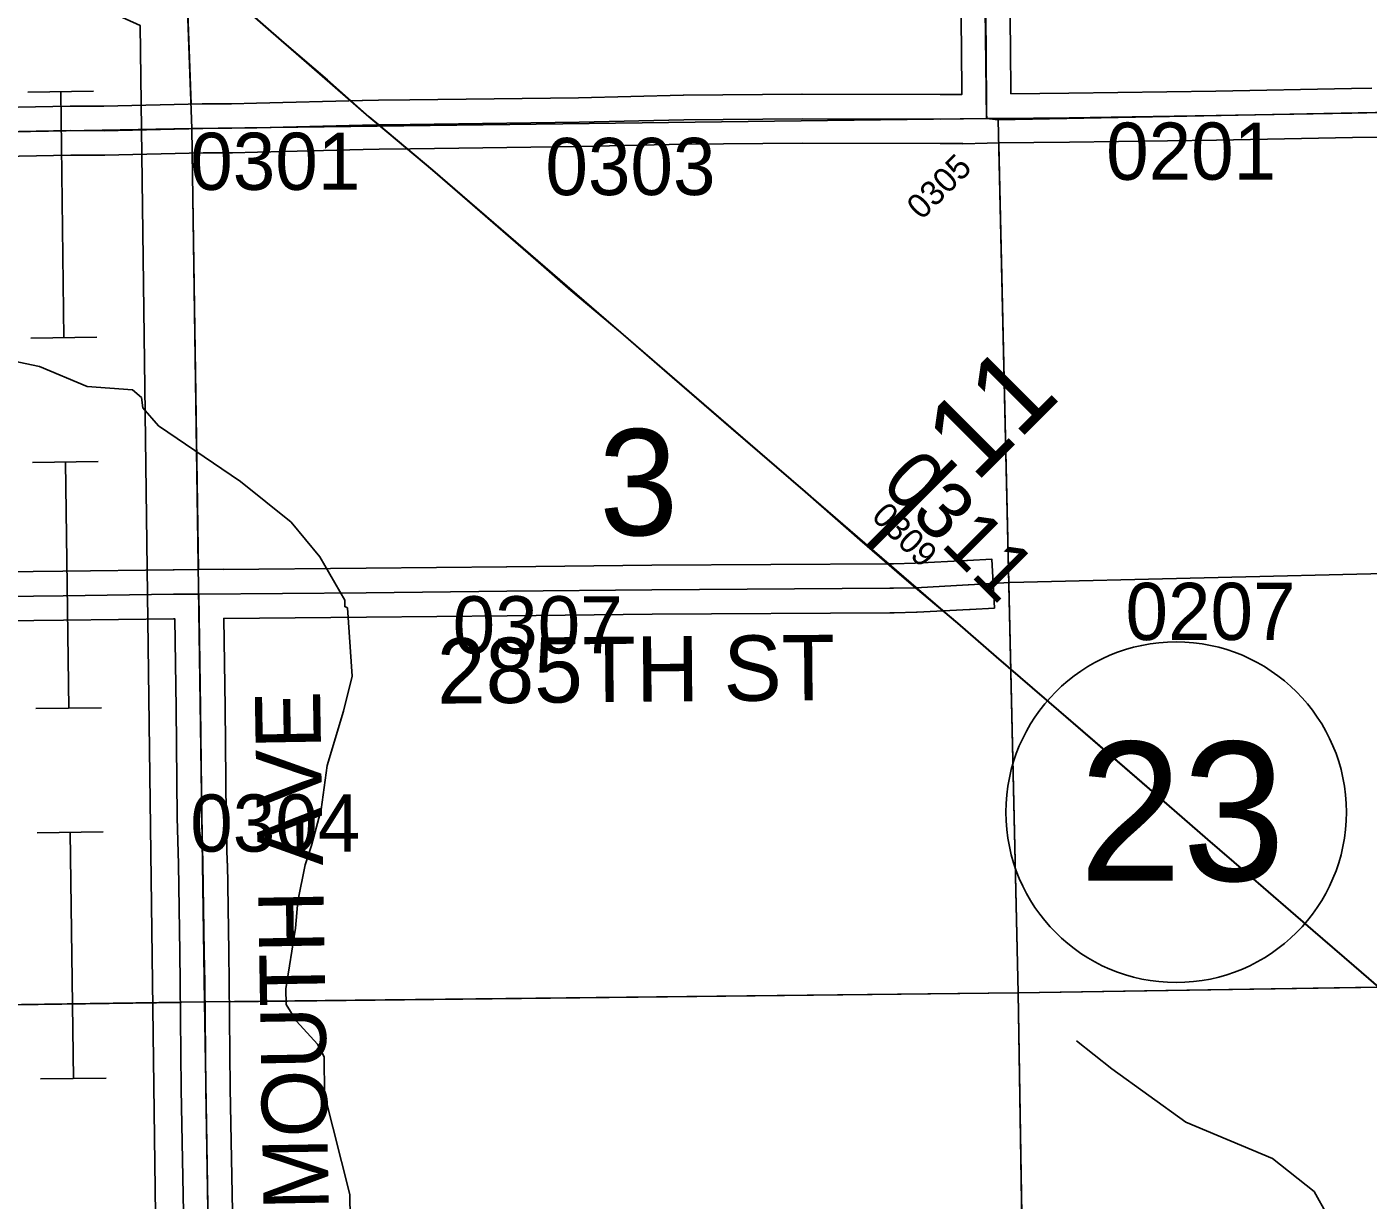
# Model space of a CAD drawing. Extents: x 23.6 to 68.7, y -63 to -29.
# Drawn here: x 47.529 to 49.171, y -52.848 to -51.412 of the extents above; entities that cross this region are included whole.
import ezdxf

# ---------------------------------------------------------------- set-up
doc = ezdxf.new("R2010")
doc.units = 0
for name, color, linetype in [('tdCoHydroRiver', 7, 'Continuous'), ('tdCoPipe', 7, 'Continuous'), ('tdCoPriCL', 7, 'Continuous'), ('tdCoPrimary', 7, 'Continuous'), ('tdCoPriNonDiv', 7, 'Continuous'), ('tdCoPriNonDivCL', 7, 'Continuous'), ('tdCoSecRdNmbr', 7, 'Continuous'), ('tdCoSecRdTxt', 7, 'Continuous'), ('tdCoSecRteBand', 7, 'Continuous'), ('tdCoSecRteCL', 7, 'Continuous'), ('tdCoSectLine', 7, 'Continuous'), ('tdCoSectLinePart', 7, 'Continuous'), ('tdCoSectNmbr', 7, 'Continuous'), ('tdCoShieldStRte', 7, 'Continuous'), ('tdCoSurfGravel', 7, 'Continuous'), ('tdCoSurfLNO', 7, 'Continuous'), ('tdCoTwpBndryShd', 7, 'Continuous'), ('tdStHwyPriRefPost1', 7, 'Continuous')]:
    doc.layers.add(name, color=color, linetype=linetype)

msp = doc.modelspace()

# ---------------------------------------------------------------- linework, layer by layer
at = {"layer": 'tdCoHydroRiver'}
for points in [[(47.9252, -52.8997), (47.9245, -52.8413), (47.8932, -52.7185), (47.8927, -52.6728), (47.8846, -52.6571), (47.8591, -52.6289), (47.8462, -52.6085), (47.846, -52.5896), (47.8578, -52.5153), (47.8606, -52.4821), (47.8696, -52.4378), (47.8772, -52.414), (47.8894, -52.3697), (47.8967, -52.316), (47.9165, -52.2494), (47.9271, -52.2067), (47.9214, -52.1231), (47.9182, -52.1215), (47.9181, -52.1137), (47.8876, -52.0603), (47.8524, -52.0181), (47.7903, -51.9682), (47.6901, -51.8999), (47.6709, -51.878), (47.6692, -51.8654), (47.658, -51.856), (47.6027, -51.8519), (47.5441, -51.8273), (47.4934, -51.8168)], [(49.1807, -52.9507), (49.1472, -52.9179), (49.136, -52.9038), (49.1359, -52.8975), (49.1295, -52.8913), (49.1214, -52.8661), (49.1053, -52.8378), (49.0543, -52.7974), (48.9481, -52.7527), (48.8574, -52.6874), (48.8144, -52.6532)]]:
    msp.add_lwpolyline(points, dxfattribs=at)
at = {"layer": 'tdCoPipe'}
for p, q in [((47.5299, -51.4914), (47.6104, -51.4904)), ((47.5338, -51.7928), (47.6145, -51.7917)), ((47.5358, -51.9449), (47.6163, -51.9439)), ((47.5396, -52.2462), (47.6203, -52.2452)), ((47.5416, -52.3984), (47.6221, -52.3974)), ((47.5455, -52.6997), (47.6261, -52.6987))]:
    msp.add_line(p, q, dxfattribs=at)
for points in [[(47.6047, -46.6586), (47.5572, -46.6597), (47.5935, -51.1509), (47.5318, -51.225), (47.5319, -51.3484), (47.5319, -51.3484), (47.6677, -51.41), (47.7455, -57.4574)], [(47.5702, -51.4909), (47.5741, -51.7922)], [(47.5761, -51.9444), (47.58, -52.2457)], [(47.5819, -52.3979), (47.5858, -52.6992)]]:
    msp.add_lwpolyline(points, dxfattribs=at)
at = {"layer": 'tdCoPriCL'}
msp.add_lwpolyline([(49.1885, -52.5912), (49.1541, -52.5615), (49.1038, -52.518), (49.0216, -52.4471), (48.9749, -52.4065), (48.9153, -52.3546), (48.8363, -52.2866), (48.7328, -52.1973), (48.716, -52.1828), (48.6684, -52.1416), (48.6172, -52.0984), (48.6033, -52.0866), (48.549, -52.0395), (48.4819, -51.9811), (48.3914, -51.9031), (48.3189, -51.8405), (48.2561, -51.786), (48.1949, -51.7345), (48.152, -51.697), (48.0684, -51.6242), (48.0257, -51.5872), (47.9593, -51.5315), (47.9476, -51.5216), (47.8965, -51.4765), (47.8437, -51.4311), (47.7922, -51.386)], dxfattribs=at)
at = {"layer": 'tdCoPrimary'}
msp.add_lwpolyline([(49.2383, -52.6339), (49.1545, -52.5615), (49.1042, -52.518), (49.022, -52.4471), (48.9753, -52.4065), (48.9157, -52.3546), (48.8367, -52.2866), (48.7164, -52.1828), (48.6688, -52.1416), (48.6176, -52.0984), (48.6037, -52.0866), (48.5494, -52.0395), (48.4823, -51.9811), (48.3918, -51.9031), (48.3193, -51.8405), (48.2564, -51.7858), (48.2564, -51.786), (48.1953, -51.7345), (48.1524, -51.697), (48.0688, -51.6242), (48.0261, -51.5872), (47.9597, -51.5315), (47.9479, -51.5216), (47.8969, -51.4765), (47.8441, -51.4311), (47.7926, -51.386)], dxfattribs=at)
msp.add_lwpolyline([(49.2383, -52.6339), (49.1545, -52.5615), (49.1042, -52.518), (49.022, -52.4471), (48.9753, -52.4065), (48.9157, -52.3546), (48.8367, -52.2866), (48.7164, -52.1828), (48.6688, -52.1416), (48.6176, -52.0984), (48.6037, -52.0866), (48.5494, -52.0395), (48.4823, -51.9811), (48.3918, -51.9031), (48.3193, -51.8405), (48.2564, -51.7858), (48.2564, -51.786), (48.1953, -51.7345), (48.1524, -51.697), (48.0688, -51.6242), (48.0261, -51.5872), (47.9597, -51.5315), (47.9479, -51.5216), (47.8969, -51.4765), (47.8441, -51.4311), (47.7926, -51.386)], dxfattribs=at)
msp.add_lwpolyline([(49.2383, -52.6339), (49.1545, -52.5615), (49.1042, -52.518), (49.022, -52.4471), (48.9753, -52.4065), (48.9157, -52.3546), (48.8367, -52.2866), (48.7164, -52.1828), (48.6688, -52.1416), (48.6176, -52.0984), (48.6037, -52.0866), (48.5494, -52.0395), (48.4823, -51.9811), (48.3918, -51.9031), (48.3193, -51.8405), (48.2564, -51.7858), (48.2564, -51.786), (48.1953, -51.7345), (48.1524, -51.697), (48.0688, -51.6242), (48.0261, -51.5872), (47.9597, -51.5315), (47.9479, -51.5216), (47.8969, -51.4765), (47.8441, -51.4311), (47.7926, -51.386)], dxfattribs=at)
at = {"layer": 'tdCoPriNonDiv'}
msp.add_lwpolyline([(49.8073, -53.1241), (49.1541, -52.5615), (48.6684, -52.1416), (48.2561, -51.786), (48.0258, -51.5872), (47.9476, -51.5216), (47.7922, -51.386), (47.4933, -51.1305), (47.2517, -50.9216), (47.0504, -50.75), (46.8721, -50.5978), (46.6907, -50.4385), (46.5932, -50.3553), (46.427, -50.2102), (46.3188, -50.1179), (46.2717, -50.0765), (46.1163, -49.9424), (45.9086, -49.7346)], dxfattribs=at)
at = {"layer": 'tdCoPriNonDivCL'}
msp.add_lwpolyline([(49.2379, -52.6339), (49.1541, -52.5615), (49.1038, -52.518), (49.0216, -52.4471), (48.9749, -52.4065), (48.9153, -52.3546), (48.8363, -52.2866), (48.716, -52.1828), (48.6684, -52.1416), (48.6172, -52.0984), (48.6033, -52.0866), (48.549, -52.0395), (48.4819, -51.9811), (48.3914, -51.9031), (48.3189, -51.8405), (48.2561, -51.7858), (48.2561, -51.786), (48.1949, -51.7345), (48.152, -51.697), (48.0684, -51.6242), (48.0257, -51.5872), (47.9593, -51.5315), (47.9476, -51.5216), (47.8965, -51.4765), (47.8437, -51.4311), (47.7922, -51.386)], dxfattribs=at)
msp.add_lwpolyline([(49.2379, -52.6339), (49.1541, -52.5615), (49.1038, -52.518), (49.0216, -52.4471), (48.9749, -52.4065), (48.9153, -52.3546), (48.8363, -52.2866), (48.716, -52.1828), (48.6684, -52.1416), (48.6172, -52.0984), (48.6033, -52.0866), (48.549, -52.0395), (48.4819, -51.9811), (48.3914, -51.9031), (48.3189, -51.8405), (48.2561, -51.7858), (48.2561, -51.786), (48.1949, -51.7345), (48.152, -51.697), (48.0684, -51.6242), (48.0257, -51.5872), (47.9593, -51.5315), (47.9476, -51.5216), (47.8965, -51.4765), (47.8437, -51.4311), (47.7922, -51.386)], dxfattribs=at)
at = {"layer": 'tdCoSecRteBand'}
for points in [[(47.4545, -51.5111), (47.5819, -51.5086), (47.5823, -51.5086), (47.5826, -51.5086), (47.6231, -51.5088), (47.7434, -51.5058), (47.7437, -51.5058), (47.744, -51.5058), (47.7796, -51.5056), (47.8099, -51.505), (47.9393, -51.5018), (47.9395, -51.5018), (47.9397, -51.5018), (47.9593, -51.5015), (47.9978, -51.501), (48.2044, -51.4983), (48.3327, -51.4953), (48.3329, -51.4953), (48.3331, -51.4953), (48.4781, -51.494), (48.4783, -51.494), (48.4784, -51.494), (48.6474, -51.4945), (48.6739, -51.4942), (48.6735, -51.4369), (48.6723, -51.3485)], [(48.7323, -51.3478), (48.7335, -51.4362), (48.7335, -51.4363), (48.7335, -51.4363), (48.7339, -51.4936)], [(48.7339, -51.4936), (48.734, -51.4936), (48.805, -51.4928), (48.9849, -51.4902), (49.151, -51.4872), (49.176, -51.4867)], [(49.1845, -51.5465), (49.1522, -51.5472), (49.1522, -51.5472), (49.1521, -51.5472), (48.9859, -51.5502), (48.9859, -51.5502), (48.9858, -51.5502), (48.8058, -51.5528), (48.8057, -51.5528), (48.8057, -51.5528), (48.7183, -51.5537), (48.7048, -51.5539), (48.675, -51.5546), (48.675, -51.5542), (48.6478, -51.5545), (48.6476, -51.5545), (48.6474, -51.5545), (48.4785, -51.554), (48.3338, -51.5553), (48.2056, -51.5582), (48.2055, -51.5582), (48.2054, -51.5582), (47.9986, -51.561), (47.9986, -51.561), (47.9986, -51.561), (47.9601, -51.5615), (47.9406, -51.5617), (47.8113, -51.5649), (47.8113, -51.5649), (47.8112, -51.5649), (47.7806, -51.5656), (47.7804, -51.5656), (47.7801, -51.5656), (47.7446, -51.5658), (47.6242, -51.5688), (47.6238, -51.5688), (47.6233, -51.5688), (47.5827, -51.5686), (47.4555, -51.5711)], [(47.3916, -52.0801), (47.573, -52.0781), (47.7078, -52.0764), (47.7079, -52.0764), (47.708, -52.0764), (47.7093, -52.0764), (47.7392, -52.0761), (47.7691, -52.0757), (47.7691, -52.0759), (47.7693, -52.0759), (47.9442, -52.0744), (48.1165, -52.0727), (48.1165, -52.0727), (48.1165, -52.0727), (48.294, -52.0709), (48.2941, -52.0709), (48.2941, -52.0709), (48.5855, -52.069), (48.5855, -52.069), (48.5856, -52.069), (48.59, -52.0689), (48.6165, -52.0684), (48.6801, -52.0649), (48.6806, -52.0649), (48.7105, -52.0633), (48.7138, -52.1232), (48.6839, -52.1248), (48.6834, -52.1249), (48.6193, -52.1284), (48.6187, -52.1284), (48.6182, -52.1284), (48.5909, -52.1289), (48.5907, -52.1289), (48.5904, -52.1289), (48.5858, -52.129), (48.2946, -52.1309), (48.1171, -52.1326), (47.9448, -52.1344), (47.9448, -52.1344), (47.9448, -52.1344), (47.7699, -52.1359), (47.7715, -52.2448), (47.7715, -52.2449), (47.7715, -52.2449), (47.773, -52.3783), (47.7743, -52.4355), (47.7743, -52.4356), (47.7744, -52.4357), (47.7761, -52.5443), (47.7761, -52.5444), (47.7761, -52.5445), (47.7766, -52.5814), (47.7766, -52.5814), (47.7766, -52.5815), (47.7779, -52.7113), (47.7809, -52.8839)], [(47.721, -52.8849), (47.7179, -52.7123), (47.7179, -52.7122), (47.7179, -52.7121), (47.7166, -52.5821), (47.7161, -52.5452), (47.7144, -52.4368), (47.713, -52.3795), (47.713, -52.3793), (47.713, -52.3791), (47.7115, -52.2457), (47.7099, -52.1364), (47.7085, -52.1364), (47.5737, -52.1381), (47.5737, -52.1381), (47.5737, -52.1381), (47.3922, -52.1401)]]:
    msp.add_lwpolyline(points, dxfattribs=at)
at = {"layer": 'tdCoSecRteCL'}
for points in [[(48.7043, -51.5239), (48.7041, -51.5171), (48.7035, -51.4366), (48.7023, -51.3481), (48.7015, -51.2538), (48.7003, -51.1515), (48.6994, -51.0484), (48.6977, -50.9522), (48.6959, -50.8442), (48.6954, -50.7492), (48.6939, -50.6326), (48.6926, -50.547), (48.6921, -50.5199)], [(48.7043, -51.5239), (48.718, -51.5237), (48.8054, -51.5228), (48.9854, -51.5202), (49.1516, -51.5172), (49.2065, -51.5161)], [(46.8485, -51.5519), (46.8522, -51.5518), (46.8896, -51.5524), (46.9323, -51.5514), (47.0134, -51.5508), (47.0885, -51.5493), (47.2004, -51.5463), (47.2721, -51.5449), (47.3844, -51.5417), (47.4549, -51.5411), (47.5825, -51.5386), (47.6235, -51.5388), (47.7441, -51.5358), (47.78, -51.5356), (47.8106, -51.535), (47.94, -51.5318), (47.9597, -51.5315), (47.9982, -51.531), (48.205, -51.5282), (48.3334, -51.5253), (48.4784, -51.524), (48.6475, -51.5245), (48.7043, -51.5239)], [(46.9835, -52.1126), (47.008, -52.1118), (47.1523, -52.1121), (47.2751, -52.1111), (47.3919, -52.1101), (47.5733, -52.1081), (47.7082, -52.1064), (47.7395, -52.1061)], [(47.7395, -52.1061), (47.9445, -52.1044), (48.1168, -52.1027), (48.2943, -52.1009), (48.5857, -52.099), (48.5903, -52.0989), (48.6176, -52.0984), (48.6818, -52.0949), (48.6822, -52.0949)], [(47.7542, -53.1048), (47.7538, -53.081), (47.7532, -53.0401), (47.751, -52.8844), (47.7479, -52.7118), (47.7466, -52.5818), (47.7461, -52.5448), (47.7444, -52.4362), (47.743, -52.3788), (47.7415, -52.2453), (47.7395, -52.1061)]]:
    msp.add_lwpolyline(points, dxfattribs=at)
at = {"layer": 'tdCoSectLine'}
for points in [[(48.6917, -50.5199), (48.704, -51.5239)], [(47.6946, -50.539), (47.7309, -51.5361)], [(48.7183, -51.5255), (49.7053, -51.5063)], [(47.7309, -51.5361), (48.704, -51.5239)], [(48.704, -51.5239), (48.7183, -51.5255)], [(48.7183, -51.5255), (48.743, -52.5943)], [(46.7201, -51.5546), (47.7309, -51.5361)], [(47.7309, -51.5361), (47.7464, -52.6056)], [(48.743, -52.5943), (49.7398, -52.579)], [(47.7464, -52.6056), (48.743, -52.5943)], [(48.743, -52.5943), (48.7589, -53.5904)], [(46.7374, -52.6201), (47.7464, -52.6056)], [(47.7464, -52.6056), (47.7625, -53.6025)]]:
    msp.add_lwpolyline(points, dxfattribs=at)
at = {"layer": 'tdCoSectLinePart'}
for points in [[(47.6956, -50.5685), (47.7299, -51.5064)], [(48.719, -51.5555), (48.743, -52.5943)], [(47.7314, -51.5664), (47.7388, -52.0765)], [(47.7765, -52.6053), (48.743, -52.5943)], [(48.743, -52.5943), (49.2076, -52.5872)], [(48.743, -52.5943), (48.7505, -53.0635)], [(47.0206, -52.6161), (47.7167, -52.6061)]]:
    msp.add_lwpolyline(points, dxfattribs=at)
at = {"layer": 'tdCoShieldStRte'}
msp.add_circle((48.9363, -52.3732), 0.2085, dxfattribs=at)
at = {"layer": 'tdCoSurfGravel'}
for points in [[(48.7043, -51.5239), (48.7041, -51.5171), (48.7035, -51.4366), (48.7023, -51.3481)], [(47.9597, -51.5315), (47.9982, -51.531), (48.205, -51.5282), (48.3334, -51.5253), (48.4784, -51.524), (48.6475, -51.5245), (48.7043, -51.5239), (48.718, -51.5237), (48.8054, -51.5228), (48.9854, -51.5202), (49.1516, -51.5172), (49.2065, -51.5161)], [(46.8333, -51.56), (46.8356, -51.5578), (46.8401, -51.5539), (46.8447, -51.5521), (46.8485, -51.5519), (46.8522, -51.5518), (46.8896, -51.5524), (46.9323, -51.5514), (47.0134, -51.5508), (47.0885, -51.5493), (47.2004, -51.5463), (47.2721, -51.5449), (47.3844, -51.5417), (47.4549, -51.5411), (47.5825, -51.5386), (47.6235, -51.5388), (47.7441, -51.5358), (47.78, -51.5356), (47.8106, -51.535), (47.94, -51.5318), (47.9597, -51.5315)], [(46.9835, -52.1126), (47.008, -52.1118), (47.1523, -52.1121), (47.2751, -52.1111), (47.3919, -52.1101), (47.5733, -52.1081), (47.7082, -52.1064), (47.7395, -52.1061)], [(47.7395, -52.1061), (47.9445, -52.1044), (48.1168, -52.1027), (48.2943, -52.1009), (48.5857, -52.099), (48.5903, -52.0989), (48.6176, -52.0984)], [(47.7572, -53.2872), (47.756, -53.2088), (47.7542, -53.1048), (47.7538, -53.081), (47.7532, -53.0401), (47.751, -52.8844), (47.7479, -52.7118), (47.7466, -52.5818), (47.7461, -52.5448), (47.7444, -52.4362), (47.743, -52.3788), (47.7415, -52.2453), (47.7395, -52.1061)], [(48.6176, -52.0984), (48.6818, -52.0949), (48.6822, -52.0949)]]:
    msp.add_lwpolyline(points, dxfattribs=at)
at = {"layer": 'tdCoSurfLNO'}
for p, q in [((48.7328, -52.0921), (49.2229, -52.0801)), ((48.6822, -52.0949), (48.7328, -52.0921))]:
    msp.add_line(p, q, dxfattribs=at)
at = {"layer": 'tdCoTwpBndryShd'}
msp.add_lwpolyline([(45.7019, -51.569), (46.6986, -51.5546), (46.7201, -51.5546), (47.7309, -51.5361), (48.704, -51.5239), (48.7183, -51.5255), (49.7053, -51.5063), (50.7061, -51.4863), (51.7147, -51.4711), (52.7049, -51.4551)], dxfattribs=at)

# ---------------------------------------------------------------- texts
at = {"layer": 'tdCoSecRdNmbr'}
for s, height, rotation, p in [('0201', 0.07, 0.038, (48.8506, -51.5988)), ('0301', 0.07, 0.0371, (47.7289, -51.6112)), ('0303', 0.07, 0.0375, (48.1639, -51.6176)), ('0305', 0.03, 45.037, (48.6247, -51.649)), ('0311', 0.07, 315.0371, (48.5727, -51.9729)), ('0309', 0.03, 315.0371, (48.5619, -52.0123)), ('0207', 0.07, 0.038, (48.8743, -52.1624)), ('0307', 0.07, 0.0374, (48.0503, -52.1788)), ('0304', 0.07, 0.0371, (47.7289, -52.4215))]:
    msp.add_text(s, height=height, rotation=rotation, dxfattribs=at).set_placement(p)
at = {"layer": 'tdCoSecRdTxt'}
for s, rotation, p in [('285TH ST', 0.5255, (48.0314, -52.2403)), ('PLYMOUTH AVE', 90.9661, (47.902, -53.0622))]:
    msp.add_text(s, height=0.08, rotation=rotation, dxfattribs=at).set_placement(p)
at = {"layer": 'tdCoSectNmbr'}
msp.add_text('3', height=0.13, rotation=1.0374, dxfattribs=at).set_placement((48.2304, -52.035))
at = {"layer": 'tdCoShieldStRte'}
msp.add_text('23', height=0.17, dxfattribs=at).set_placement((48.8172, -52.4571))
at = {"layer": 'tdStHwyPriRefPost1'}
msp.add_text('‒‒11', height=0.1, rotation=45, dxfattribs=at).set_placement((48.5858, -52.0761))

doc.saveas('drawing.dxf')
